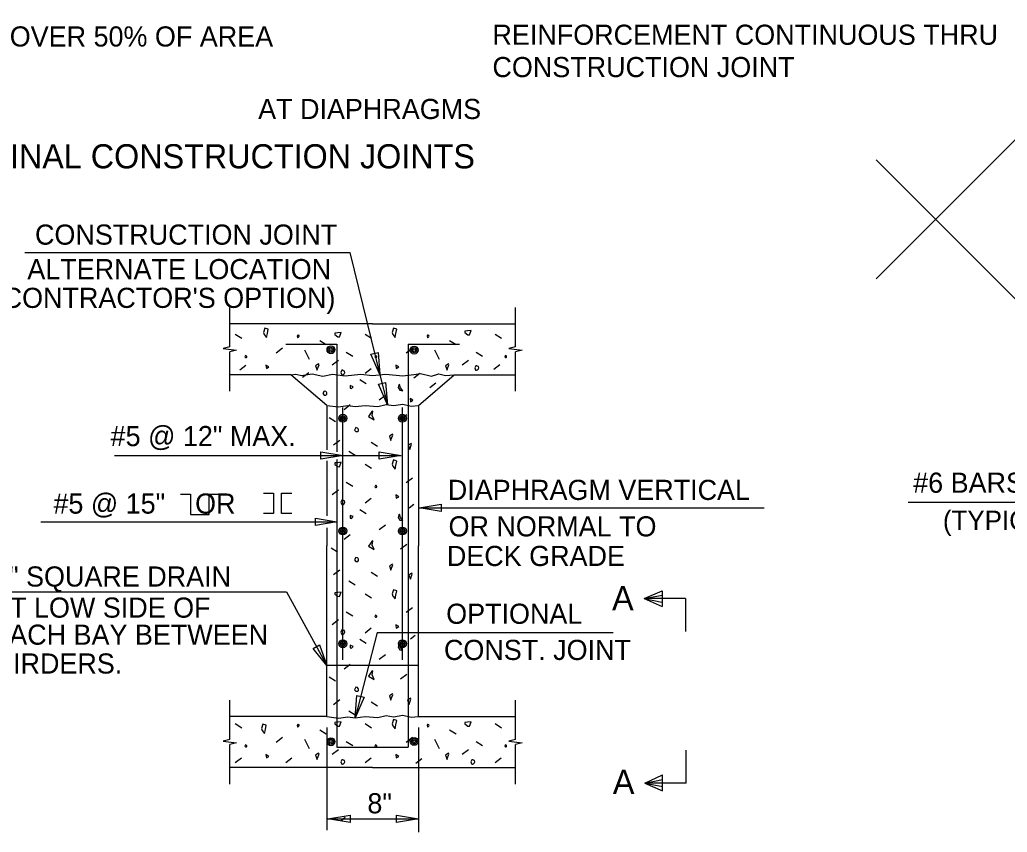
# Model space of a CAD drawing. Extents: x 0 to 34, y 0 to 23.5.
# Drawn here: x 16.55 to 24.21, y 9.27 to 15.58 of the extents above; entities that cross this region are included whole.
import ezdxf

# ---------------------------------------------------------------- set-up
doc = ezdxf.new("R2010")
doc.units = 0
for name, color, linetype in [('BRDG_ANNO_General-Notes', 7, 'Continuous'), ('BRDG_BASE_Dtlctrln', 7, 'Continuous'), ('BRDG_BASE_Hidden-Line', 7, 'Continuous'), ('BRDG_BASE_Obj-Line', 7, 'Continuous'), ('BRDG_BASE_Pattern', 7, 'Continuous'), ('BRDG_BASE_Rebar', 7, 'Continuous')]:
    doc.layers.add(name, color=color, linetype=linetype)

msp = doc.modelspace()

# ---------------------------------------------------------------- linework, layer by layer
at = {"layer": 'BRDG_ANNO_General-Notes'}
for p, q in [((16.5888, 13.7706), (19.112, 13.7706)), ((19.112, 13.7706), (19.3453, 12.8232)), ((19.2755, 12.9833), (19.3308, 12.997)), ((19.344, 12.8241), (19.2755, 12.9833)), ((19.3308, 12.997), (19.344, 12.8241)), ((19.3453, 12.8232), (19.4027, 12.5901)), ((19.3342, 12.7493), (19.3895, 12.763)), ((19.4027, 12.5901), (19.3342, 12.7493)), ((19.3895, 12.763), (19.4027, 12.5901)), ((17.2847, 12.1969), (19.0589, 12.1969)), ((18.8879, 12.1684), (18.8879, 12.2254)), ((18.8879, 12.2254), (19.0589, 12.1969)), ((19.0589, 12.1969), (18.8879, 12.1684)), ((19.0589, 12.1969), (19.5095, 12.1969)), ((19.3385, 12.1684), (19.3385, 12.2254)), ((19.3385, 12.2254), (19.5095, 12.1969)), ((19.5095, 12.1969), (19.3385, 12.1684)), ((19.438, 12.206), (19.4592, 12.1883)), ((19.6503, 11.7911), (19.8213, 11.8196)), ((19.8213, 11.8196), (19.8213, 11.7626)), ((23.443, 11.834), (25.2769, 11.834)), ((19.6503, 11.7911), (22.3278, 11.7911)), ((19.8213, 11.7626), (19.6503, 11.7911)), ((16.713, 11.6814), (19.0114, 11.6814)), ((18.8444, 11.6535), (18.8444, 11.7092)), ((18.8444, 11.7092), (19.0114, 11.6814)), ((19.0114, 11.6814), (18.8444, 11.6535)), ((16.3274, 11.1383), (18.6193, 11.1383)), ((18.6193, 11.1383), (18.9322, 10.5657)), ((21.3967, 11.0871), (21.5353, 11.1472)), ((21.3967, 11.0871), (21.5359, 11.1129)), ((21.5353, 11.1472), (21.5353, 11.0231)), ((21.7167, 11.0871), (21.3967, 11.0871)), ((21.3967, 11.0871), (21.5353, 11.0231)), ((21.3967, 11.0871), (21.533, 11.0574)), ((21.7167, 11.0871), (21.7167, 10.8311)), ((19.3241, 10.8222), (19.1518, 10.1611)), ((19.3241, 10.8222), (21.1538, 10.8222)), ((18.8277, 10.6989), (18.8766, 10.7256)), ((18.9322, 10.5657), (18.8277, 10.6989)), ((18.8766, 10.7256), (18.9322, 10.5657)), ((19.1518, 10.1611), (19.1673, 10.3338)), ((19.2226, 10.3194), (19.1518, 10.1611)), ((19.1673, 10.3338), (19.2226, 10.3194)), ((18.9322, 10.0863), (18.9322, 9.2878)), ((19.6447, 10.0863), (19.6447, 9.2722)), ((21.7205, 9.6528), (21.7205, 9.9088)), ((21.4005, 9.6528), (21.5391, 9.7168)), ((21.4005, 9.6528), (21.5368, 9.6824)), ((21.5391, 9.5927), (21.5391, 9.7168)), ((21.7205, 9.6528), (21.4005, 9.6528)), ((21.4005, 9.6528), (21.5391, 9.5927)), ((21.4005, 9.6528), (21.5398, 9.627)), ((18.9421, 9.3764), (19.1131, 9.4049)), ((18.9421, 9.3764), (19.6447, 9.3764)), ((19.1131, 9.3479), (18.9421, 9.3764)), ((19.0759, 9.3869), (19.0406, 9.3586)), ((19.1131, 9.4049), (19.1131, 9.3479)), ((19.4737, 9.3479), (19.4737, 9.4049)), ((19.4737, 9.4049), (19.6447, 9.3764)), ((19.6447, 9.3764), (19.4737, 9.3479))]:
    msp.add_line(p, q, dxfattribs=at)
at = {"layer": 'BRDG_BASE_Dtlctrln'}
for p, q in [((19.0572, 10.6105), (19.0572, 12.5689)), ((19.5197, 10.6105), (19.5197, 12.5689))]:
    msp.add_line(p, q, dxfattribs=at)
at = {"layer": 'BRDG_BASE_Hidden-Line'}
msp.add_line((19.6447, 10.5657), (18.9322, 10.5657), dxfattribs=at)
at = {"layer": 'BRDG_BASE_Obj-Line'}
for p, q in [((18.1801, 13.0394), (18.1801, 13.3454)), ((20.3968, 13.0394), (20.3968, 13.3454)), ((19.2884, 13.2178), (18.1801, 13.2178)), ((19.2884, 13.2178), (20.3968, 13.2178)), ((18.1801, 13.0394), (18.128, 13.0264)), ((18.128, 13.0264), (18.2322, 13.0134)), ((20.3968, 13.0394), (20.3447, 13.0264)), ((20.3447, 13.0264), (20.4489, 13.0134)), ((18.2322, 13.0134), (18.1801, 13.0004)), ((18.1801, 12.6944), (18.1801, 13.0004)), ((20.4489, 13.0134), (20.3968, 13.0004)), ((20.3968, 12.6944), (20.3968, 13.0004)), ((18.6551, 12.822), (18.1801, 12.822)), ((18.9322, 12.5845), (18.6551, 12.822)), ((19.6447, 12.5845), (19.9218, 12.822)), ((19.9218, 12.822), (20.3968, 12.822)), ((18.9322, 12.5845), (18.9322, 12.241)), ((19.6447, 12.5845), (19.6447, 11.4959)), ((18.9322, 12.1543), (18.9322, 11.7272)), ((18.9322, 11.6347), (18.9322, 11.4959)), ((18.9322, 10.1699), (18.9322, 11.4959)), ((19.6447, 10.1699), (19.6447, 11.4959)), ((18.1801, 9.9915), (18.1801, 10.2975)), ((20.3968, 9.9915), (20.3968, 10.2975)), ((18.9322, 10.1699), (18.1801, 10.1699)), ((19.6447, 10.1699), (20.3968, 10.1699)), ((18.1801, 9.9915), (18.128, 9.9785)), ((18.128, 9.9785), (18.2322, 9.9655)), ((18.2322, 9.9655), (18.1801, 9.9524)), ((20.3968, 9.9915), (20.3447, 9.9785)), ((20.3447, 9.9785), (20.4489, 9.9655)), ((20.4489, 9.9655), (20.3968, 9.9524)), ((18.1801, 9.6465), (18.1801, 9.9524)), ((20.3968, 9.6465), (20.3968, 9.9524)), ((19.2884, 9.7741), (18.1801, 9.7741)), ((19.2884, 9.7741), (20.3968, 9.7741))]:
    msp.add_line(p, q, dxfattribs=at)
for points in [[(18.6551, 12.822), (18.6934, 12.8279), (18.7357, 12.816), (18.8186, 12.8297), (18.9016, 12.8114), (18.9765, 12.8279), (19.0757, 12.8151), (19.196, 12.8279), (19.2871, 12.816), (19.3912, 12.8288), (19.523, 12.8141), (19.6096, 12.8241), (19.6612, 12.8316), (19.7458, 12.8123), (19.8011, 12.8306), (19.8531, 12.816), (19.9218, 12.822)], [(18.9322, 12.5845), (19.0235, 12.5748), (19.0957, 12.5839), (19.1531, 12.5769), (19.2318, 12.5853), (19.3286, 12.5776), (19.3926, 12.5915), (19.45, 12.5839), (19.5221, 12.5943), (19.5878, 12.5804), (19.6447, 12.5845)], [(18.9322, 10.1699), (19.0235, 10.1585), (19.0957, 10.1692), (19.1531, 10.1609), (19.2318, 10.1708), (19.3286, 10.1618), (19.3926, 10.1782), (19.45, 10.1692), (19.5221, 10.1815), (19.5878, 10.1651), (19.6447, 10.1699)]]:
    msp.add_lwpolyline(points, dxfattribs=at)
at = {"layer": 'BRDG_BASE_Pattern'}
for p, q in [((18.2232, 13.1371), (18.2727, 13.1058)), ((19.2316, 13.1371), (19.281, 13.1058)), ((20.24, 13.1371), (20.2894, 13.1058)), ((18.5889, 13.0284), (18.5407, 12.9918)), ((18.8779, 13.0881), (18.9274, 13.0568)), ((19.5972, 13.0284), (19.5491, 12.9918)), ((19.8863, 13.0881), (19.9358, 13.0568)), ((18.7604, 13.0173), (18.7971, 12.9437)), ((19.0843, 12.9978), (19.1337, 12.9665)), ((19.7688, 13.0173), (19.8055, 12.9437)), ((20.0927, 12.9978), (20.1421, 12.9665)), ((18.306, 12.8953), (18.2579, 12.8587)), ((19.0238, 12.9346), (18.9757, 12.898)), ((20.0322, 12.9346), (19.9841, 12.898)), ((20.2766, 12.9004), (20.2284, 12.8638)), ((18.7936, 12.8388), (18.7455, 12.8022)), ((19.2784, 12.8696), (19.2303, 12.833)), ((19.6556, 12.8327), (19.6074, 12.7961)), ((19.1885, 12.7857), (19.238, 12.7544)), ((19.7798, 12.7587), (19.7317, 12.7221)), ((19.3887, 12.6632), (19.3406, 12.6266)), ((19.1152, 12.5885), (19.0671, 12.5519)), ((18.9522, 12.4924), (19.0017, 12.4612)), ((19.5538, 12.512), (19.5057, 12.4754)), ((19.0341, 12.3137), (18.986, 12.2771)), ((19.2766, 12.2988), (19.326, 12.2678)), ((19.103, 12.2305), (19.1526, 12.1993)), ((19.2316, 12.1298), (19.281, 12.0985)), ((19.0843, 11.9904), (19.1337, 11.9592)), ((19.5972, 12.021), (19.5491, 11.9844)), ((19.0238, 11.9273), (18.9757, 11.8907)), ((19.2784, 11.8623), (19.2303, 11.8257)), ((19.6088, 11.8171), (19.5716, 11.7888)), ((19.1885, 11.7783), (19.238, 11.7471)), ((19.3887, 11.6558), (19.3406, 11.6192)), ((19.1152, 11.5811), (19.0671, 11.5445)), ((19.5538, 11.5047), (19.5057, 11.4681)), ((18.9676, 11.4799), (19.0171, 11.4487)), ((19.0341, 11.3064), (18.986, 11.2698)), ((19.2766, 11.2915), (19.326, 11.2604)), ((19.103, 11.2232), (19.1526, 11.1919)), ((19.2316, 11.1224), (19.281, 11.0911)), ((19.0843, 10.9831), (19.1337, 10.9518)), ((19.5972, 11.0137), (19.5491, 10.9771)), ((19.0238, 10.9199), (18.9757, 10.8833)), ((19.2784, 10.8549), (19.2303, 10.8183)), ((19.1885, 10.771), (19.238, 10.7397)), ((19.619, 10.7994), (19.5818, 10.7711)), ((19.3887, 10.6485), (19.3406, 10.6119)), ((19.1152, 10.5738), (19.0671, 10.5372)), ((18.9522, 10.4777), (19.0017, 10.4465)), ((19.5538, 10.4973), (19.5057, 10.4607)), ((19.0341, 10.2991), (18.986, 10.2624)), ((19.2766, 10.2841), (19.326, 10.2531)), ((19.103, 10.2158), (19.1526, 10.1846)), ((18.2232, 10.1151), (18.2727, 10.0838)), ((19.2316, 10.1151), (19.281, 10.0838)), ((20.24, 10.1151), (20.2894, 10.0838)), ((18.8779, 10.066), (18.9274, 10.0348)), ((19.8863, 10.066), (19.9358, 10.0348)), ((18.5889, 10.0064), (18.5407, 9.9697)), ((18.7604, 9.9953), (18.7971, 9.9217)), ((19.0843, 9.9757), (19.1337, 9.9445)), ((19.5972, 10.0064), (19.5491, 9.9697)), ((19.7688, 9.9953), (19.8055, 9.9217)), ((20.0927, 9.9757), (20.1421, 9.9445)), ((19.0238, 9.9126), (18.9757, 9.876)), ((20.0322, 9.9126), (19.9841, 9.876)), ((18.2701, 9.8476), (18.2219, 9.811)), ((18.6626, 9.8466), (18.6145, 9.81)), ((19.2784, 9.8476), (19.2303, 9.811)), ((19.671, 9.8415), (19.6229, 9.8049)), ((20.2868, 9.8476), (20.2387, 9.811))]:
    msp.add_line(p, q, dxfattribs=at)
for points in [[(18.4533, 13.1849), (18.4421, 13.1518), (18.4478, 13.1353), (18.4643, 13.1131), (18.4717, 13.1426), (18.4772, 13.1758)], [(19.4514, 13.1849), (19.4402, 13.1518), (19.4459, 13.1352), (19.4624, 13.1131), (19.4698, 13.1426), (19.4753, 13.1757)], [(18.7034, 13.1223), (18.7064, 13.1131), (18.709, 13.1131), (18.7128, 13.114), (18.7155, 13.1167), (18.7181, 13.1223), (18.7174, 13.1278), (18.7128, 13.1288), (18.7108, 13.1307), (18.7071, 13.1307)], [(19.0177, 13.1476), (18.9956, 13.1457), (18.9956, 13.1347), (19.0195, 13.1182), (19.0325, 13.1163), (19.0454, 13.1512)], [(19.7118, 13.1223), (19.7147, 13.1131), (19.7174, 13.1131), (19.7211, 13.114), (19.7239, 13.1167), (19.7265, 13.1223), (19.7258, 13.1278), (19.7211, 13.1288), (19.7192, 13.1307), (19.7155, 13.1307)], [(20.026, 13.163), (20.004, 13.1611), (20.004, 13.1501), (20.0279, 13.1336), (20.0409, 13.1317), (20.0538, 13.1667)], [(18.3015, 12.9717), (18.2969, 12.9615), (18.3023, 12.9559), (18.3089, 12.9559), (18.3116, 12.9589), (18.3116, 12.9643), (18.3107, 12.9669), (18.3079, 12.9699)], [(19.3099, 12.9717), (19.3053, 12.9615), (19.3107, 12.9559), (19.3173, 12.9559), (19.32, 12.9589), (19.32, 12.9643), (19.3191, 12.9669), (19.3163, 12.9699)], [(20.3183, 12.9717), (20.3136, 12.9615), (20.3191, 12.9559), (20.3257, 12.9559), (20.3284, 12.9589), (20.3284, 12.9643), (20.3275, 12.9669), (20.3246, 12.9699)], [(18.4604, 12.8979), (18.4641, 12.8721), (18.4826, 12.8832)], [(18.8465, 12.8925), (18.8579, 12.8593), (18.8579, 12.8629), (18.8726, 12.8998), (18.8688, 12.9072)], [(19.4688, 12.8979), (19.4725, 12.8721), (19.491, 12.8832)], [(19.8548, 12.8925), (19.8663, 12.8593), (19.8663, 12.8629), (19.8809, 12.8998), (19.8772, 12.9072)], [(20.0822, 12.8767), (20.0881, 12.8583), (20.0934, 12.8583), (20.1009, 12.8601), (20.1063, 12.8655), (20.1117, 12.8767), (20.1102, 12.8877), (20.1009, 12.8896), (20.097, 12.8934), (20.0896, 12.8934)], [(19.0431, 12.8408), (19.0489, 12.8223), (19.0542, 12.8223), (19.0617, 12.8242), (19.0671, 12.8295), (19.0725, 12.8408), (19.071, 12.8517), (19.0617, 12.8536), (19.0578, 12.8574), (19.0505, 12.8574)], [(19.1148, 12.7383), (19.1139, 12.7185), (19.1258, 12.7158), (19.1373, 12.7291)], [(19.4913, 12.7438), (19.4872, 12.7231), (19.5009, 12.7028), (19.524, 12.6982), (19.5056, 12.7226), (19.4977, 12.7479)], [(18.9118, 12.6967), (18.9026, 12.6765), (18.9134, 12.6653), (18.9266, 12.6653), (18.932, 12.6711), (18.932, 12.6819), (18.9302, 12.6872), (18.9245, 12.6932)], [(19.579, 12.6396), (19.5827, 12.6138), (19.6011, 12.6249)], [(19.2821, 12.5374), (19.2564, 12.4989), (19.2997, 12.473), (19.2839, 12.508), (19.2906, 12.5401)], [(19.1579, 12.413), (19.1486, 12.3928), (19.1594, 12.3815), (19.1727, 12.3815), (19.1781, 12.3874), (19.1781, 12.3982), (19.1762, 12.4035), (19.1705, 12.4094)], [(19.4191, 12.3466), (19.4304, 12.3133), (19.4304, 12.3169), (19.4452, 12.3539), (19.4415, 12.3613)], [(19.5651, 12.2758), (19.5765, 12.2427), (19.5765, 12.2462), (19.5911, 12.2832), (19.5874, 12.2906)], [(19.0177, 12.1403), (18.9956, 12.1384), (18.9956, 12.1273), (19.0195, 12.1108), (19.0325, 12.109), (19.0454, 12.1439)], [(19.4514, 12.1622), (19.4402, 12.1291), (19.4459, 12.1125), (19.4624, 12.0904), (19.4698, 12.1198), (19.4753, 12.153)], [(19.3099, 11.9643), (19.3053, 11.9542), (19.3107, 11.9485), (19.3173, 11.9485), (19.32, 11.9515), (19.32, 11.9569), (19.3191, 11.9596), (19.3163, 11.9626)], [(19.4688, 11.8906), (19.4725, 11.8647), (19.491, 11.8758)], [(19.0431, 11.8334), (19.0489, 11.815), (19.0542, 11.815), (19.0617, 11.8168), (19.0671, 11.8222), (19.0725, 11.8334), (19.071, 11.8444), (19.0617, 11.8463), (19.0578, 11.8501), (19.0505, 11.8501)], [(19.1148, 11.731), (19.1139, 11.7112), (19.1258, 11.7084), (19.1373, 11.7218)], [(19.4913, 11.7365), (19.4872, 11.7157), (19.5009, 11.6954), (19.524, 11.6909), (19.5056, 11.7153), (19.4977, 11.7406)], [(19.2821, 11.5301), (19.2564, 11.4916), (19.2997, 11.4656), (19.2839, 11.5007), (19.2906, 11.5328)], [(19.1579, 11.4056), (19.1486, 11.3854), (19.1594, 11.3742), (19.1727, 11.3742), (19.1781, 11.3801), (19.1781, 11.3908), (19.1762, 11.3961), (19.1705, 11.4021)], [(19.4191, 11.3392), (19.4304, 11.306), (19.4304, 11.3095), (19.4452, 11.3466), (19.4415, 11.3539)], [(19.5702, 11.2685), (19.5816, 11.2353), (19.5816, 11.2389), (19.5963, 11.2759), (19.5926, 11.2832)], [(19.0177, 11.1329), (18.9956, 11.131), (18.9956, 11.12), (19.0195, 11.1035), (19.0325, 11.1016), (19.0454, 11.1366)], [(19.4514, 11.1548), (19.4402, 11.1217), (19.4459, 11.1052), (19.4624, 11.083), (19.4698, 11.1125), (19.4753, 11.1457)], [(19.3099, 10.957), (19.3053, 10.9468), (19.3107, 10.9412), (19.3173, 10.9412), (19.32, 10.9442), (19.32, 10.9496), (19.3191, 10.9522), (19.3163, 10.9552)], [(19.4688, 10.8832), (19.4725, 10.8574), (19.491, 10.8685)], [(19.0431, 10.8261), (19.0489, 10.8077), (19.0542, 10.8077), (19.0617, 10.8095), (19.0671, 10.8148), (19.0725, 10.8261), (19.071, 10.837), (19.0617, 10.839), (19.0578, 10.8428), (19.0505, 10.8428)], [(19.4913, 10.7291), (19.4872, 10.7084), (19.5009, 10.6881), (19.524, 10.6835), (19.5056, 10.7079), (19.4977, 10.7332)], [(19.1148, 10.7236), (19.1139, 10.7039), (19.1258, 10.7011), (19.1373, 10.7144)], [(19.2821, 10.5228), (19.2564, 10.4842), (19.2997, 10.4583), (19.2839, 10.4933), (19.2906, 10.5254)], [(19.1579, 10.3983), (19.1486, 10.3781), (19.1594, 10.3668), (19.1727, 10.3668), (19.1781, 10.3727), (19.1781, 10.3835), (19.1762, 10.3888), (19.1705, 10.3947)], [(19.4191, 10.3319), (19.4304, 10.2986), (19.4304, 10.3022), (19.4452, 10.3392), (19.4415, 10.3466)], [(19.5599, 10.2971), (19.5713, 10.2639), (19.5713, 10.2674), (19.586, 10.3045), (19.5822, 10.3118)], [(19.0177, 10.1256), (18.9956, 10.1237), (18.9956, 10.1127), (19.0195, 10.0961), (19.0325, 10.0943), (19.0454, 10.1292)], [(19.4514, 10.1475), (19.4402, 10.1144), (19.4459, 10.0978), (19.4624, 10.0757), (19.4698, 10.1052), (19.4753, 10.1383)], [(20.026, 10.1256), (20.004, 10.1237), (20.004, 10.1127), (20.0279, 10.0961), (20.0409, 10.0943), (20.0538, 10.1292)], [(18.4379, 10.1116), (18.4267, 10.0784), (18.4324, 10.0619), (18.449, 10.0397), (18.4563, 10.0692), (18.4618, 10.1024)], [(18.7034, 10.1003), (18.7064, 10.091), (18.709, 10.091), (18.7128, 10.092), (18.7155, 10.0946), (18.7181, 10.1003), (18.7174, 10.1058), (18.7128, 10.1067), (18.7108, 10.1086), (18.7071, 10.1086)], [(19.7118, 10.1003), (19.7147, 10.091), (19.7174, 10.091), (19.7211, 10.092), (19.7239, 10.0946), (19.7265, 10.1003), (19.7258, 10.1058), (19.7211, 10.1067), (19.7192, 10.1086), (19.7155, 10.1086)], [(18.3015, 9.9496), (18.2969, 9.9395), (18.3023, 9.9339), (18.3089, 9.9339), (18.3116, 9.9368), (18.3116, 9.9422), (18.3107, 9.9449), (18.3079, 9.9479)], [(18.8465, 9.8705), (18.8579, 9.8372), (18.8579, 9.8408), (18.8726, 9.8778), (18.8688, 9.8852)], [(19.3099, 9.9496), (19.3053, 9.9395), (19.3107, 9.9339), (19.3173, 9.9339), (19.32, 9.9368), (19.32, 9.9422), (19.3191, 9.9449), (19.3163, 9.9479)], [(19.8548, 9.8705), (19.8663, 9.8372), (19.8663, 9.8408), (19.8809, 9.8778), (19.8772, 9.8852)], [(20.3183, 9.9496), (20.3136, 9.9395), (20.3191, 9.9339), (20.3257, 9.9339), (20.3284, 9.9368), (20.3284, 9.9422), (20.3275, 9.9449), (20.3246, 9.9479)], [(18.4604, 9.8759), (18.4641, 9.8501), (18.4826, 9.8611)], [(19.0431, 9.8187), (19.0489, 9.8003), (19.0542, 9.8003), (19.0617, 9.8021), (19.0671, 9.8075), (19.0725, 9.8187), (19.071, 9.8297), (19.0617, 9.8316), (19.0578, 9.8354), (19.0505, 9.8354)], [(19.4688, 9.8759), (19.4725, 9.8501), (19.491, 9.8611)], [(20.0515, 9.8187), (20.0573, 9.8003), (20.0626, 9.8003), (20.0701, 9.8021), (20.0755, 9.8075), (20.0809, 9.8187), (20.0794, 9.8297), (20.0701, 9.8316), (20.0662, 9.8354), (20.0589, 9.8354)]]:
    msp.add_lwpolyline(points, close=True, dxfattribs=at)
at = {"layer": 'BRDG_BASE_Rebar'}
for p, q in [((23.1948, 13.5681), (26.3226, 16.6959)), ((26.3226, 11.3639), (23.1948, 14.4917)), ((18.6155, 13.0595), (19.0114, 13.0595)), ((19.0114, 13.0595), (19.0114, 12.2241)), ((19.5655, 13.0595), (19.9614, 13.0595)), ((19.5655, 13.0595), (19.5655, 9.9324)), ((19.0114, 12.166), (19.0114, 9.9324)), ((19.0114, 9.9324), (19.5655, 9.9324))]:
    msp.add_line(p, q, dxfattribs=at)
for points in [[(17.7966, 11.8971), (17.8753, 11.8971), (17.8753, 11.7395), (18.0197, 11.7395), (18.0197, 11.8971), (18.0985, 11.8971)], [(18.4417, 11.9027), (18.5205, 11.9027), (18.5205, 11.7451), (18.4417, 11.7451)], [(18.6612, 11.7451), (18.5824, 11.7451), (18.5824, 11.9027), (18.6612, 11.9027)]]:
    msp.add_lwpolyline(points, dxfattribs=at)
for centre, radius in [((18.9651, 13.0171), 0.0305), ((18.9651, 13.0171), 0.0203), ((18.9651, 13.0171), 0.0102), ((19.6109, 13.0143), 0.0305), ((19.6109, 13.0143), 0.0203), ((19.6109, 13.0143), 0.0102), ((19.0572, 12.4855), 0.0305), ((19.0572, 12.4855), 0.0203), ((19.0572, 12.4855), 0.0102), ((19.5197, 12.4855), 0.0305), ((19.5197, 12.4855), 0.0203), ((19.5197, 12.4855), 0.0102), ((19.0572, 11.6105), 0.0305), ((19.0572, 11.6105), 0.0203), ((19.0572, 11.6105), 0.0102), ((19.5197, 11.6105), 0.0305), ((19.5197, 11.6105), 0.0203), ((19.5197, 11.6105), 0.0102), ((19.0572, 10.7355), 0.0305), ((19.0572, 10.7355), 0.0203), ((19.0572, 10.7355), 0.0102), ((19.5197, 10.7355), 0.0305), ((19.5197, 10.7355), 0.0203), ((19.5197, 10.7355), 0.0102), ((18.9651, 9.9747), 0.0305), ((18.9651, 9.9747), 0.0203), ((18.9651, 9.9747), 0.0102), ((19.6109, 9.9775), 0.0305), ((19.6109, 9.9775), 0.0203), ((19.6109, 9.9775), 0.0102)]:
    msp.add_circle(centre, radius, dxfattribs=at)

# ---------------------------------------------------------------- texts
at = {"layer": 'BRDG_ANNO_General-Notes'}
for s, height, p in [('OVER 50% OF AREA', 0.15625, (16.4729, 15.3705)), ('REINFORCEMENT CONTINUOUS THRU', 0.15625, (20.2183, 15.384)), ('CONSTRUCTION JOINT', 0.15625, (20.2183, 15.133)), ('AT DIAPHRAGMS', 0.15625, (18.4005, 14.8076)), ('LONGITUDINAL CONSTRUCTION JOINTS', 0.1875, (15.1789, 14.4248)), ('CONSTRUCTION JOINT', 0.15625, (16.6689, 13.8326)), ('ALTERNATE LOCATION', 0.15625, (16.6094, 13.5648)), ("(AT CONTRACTOR'S OPTION)", 0.15625, (16.0231, 13.3418)), ('#5 @ 12" MAX.', 0.15625, (17.2557, 12.269)), ('#6 BARS x 6\'-0"', 0.15625, (23.4831, 11.9072)), ('DIAPHRAGM VERTICAL', 0.15625, (19.8718, 11.8514)), ('#5 @ 15"    OR', 0.15625, (16.8118, 11.7452)), ('OR NORMAL TO', 0.15625, (19.8776, 11.5682)), ('(TYPICAL)', 0.15042, (23.7136, 11.6179)), ('DECK GRADE', 0.15625, (19.8648, 11.3386)), ('6" SQUARE DRAIN', 0.15625, (16.351, 11.1791)), ('A', 0.1875, (21.1465, 10.9955)), ('AT LOW SIDE OF', 0.15625, (16.336, 10.9376)), ('OPTIONAL ', 0.15625, (19.8593, 10.89)), ('EACH BAY BETWEEN', 0.15625, (16.3296, 10.7275)), ('CONST. JOINT', 0.15625, (19.8421, 10.6093)), ('GIRDERS.', 0.15625, (16.336, 10.5038)), ('A', 0.1875, (21.1527, 9.5698)), ('8"', 0.15625, (19.248, 9.4191))]:
    msp.add_text(s, height=height, dxfattribs=at).set_placement(p)

doc.saveas('drawing.dxf')
